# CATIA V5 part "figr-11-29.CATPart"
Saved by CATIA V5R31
Part number: Part1
Bounding box of the stored display mesh (mm): x -52 to 53, y -75.374 to 75.374, z 0 to 37.54
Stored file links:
  D:\PROJECTS\Project 2021\US EDITION\CATIA V5 6R 2021\Resources\Part Files\c11_catia_v5_6r2021_prt\figr-11-29.CATPart
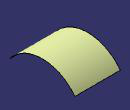
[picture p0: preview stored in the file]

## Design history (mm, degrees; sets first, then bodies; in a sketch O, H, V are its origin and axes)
Set1
  Extrude1: Element1 Sketch1, Lim1 53, Lim2 52, Direction yz-plane
Body1 (main body)
  Sketch1 on yz-plane, origin (0, 0, 0), H (0, 1, 0), V (0, 0, 1)
    arc A1 centre (0, -56.4477) radius 94.1675 from (-75.3736, 0) to (75.3736, 0) cw
    point P1 (0, -56.4477)
    point P2 (-75.3736, 0)
    point P3 (75.3736, 0)
    point P4 (0, 37.7198)
    coincidence: P2 H, P3 H, A1 P4, P4 V, P1 V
